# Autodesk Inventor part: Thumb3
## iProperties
Company: cbliss@cbliss.com
Author: Charles Bliss
Shininess: 0.0
PropertySet Name: _Private Model Information
Created: 2000-01
Part Number: Thumb3
Project: Inventor Sample
Document SubType Name: Modeling
Designer: Charles Bliss
Control State: 0
Master: False
Checked Out: False
Density: 0.0
Volume: 0.0
Area: 0.0
PropertySet Name: Model Information
